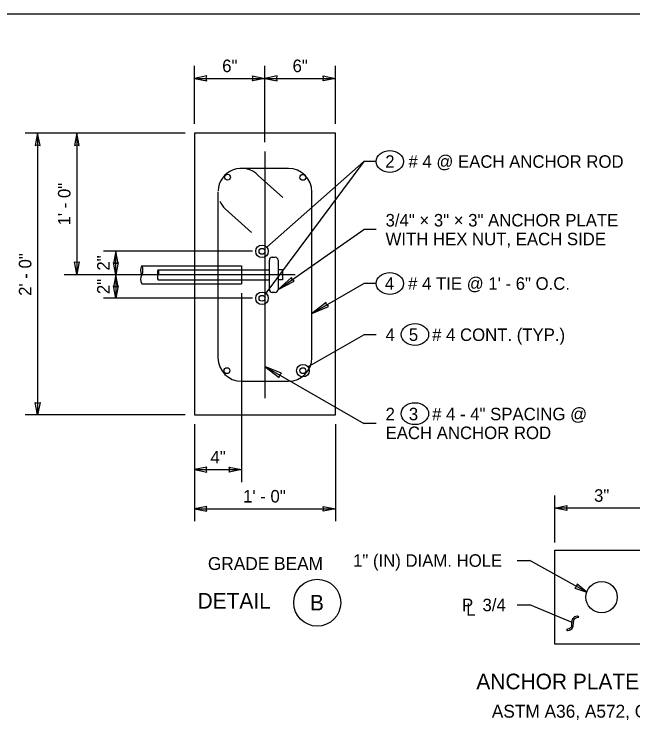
# Model space of a CAD drawing. Extents: x 99862 to 104211, y 98939 to 105076.
# Drawn here: x 101422 to 102213, y 104169 to 105076 of the extents above; entities that cross this region are included whole.
import ezdxf

# ---------------------------------------------------------------- set-up
doc = ezdxf.new("R2010")
doc.units = 0
for name, color, linetype in [('Level 1', 7, 'Continuous'), ('Level 10', 7, 'Continuous'), ('Level 12', 7, 'Continuous'), ('Level 15', 7, 'Continuous'), ('Level 18', 7, 'Continuous'), ('Level 20', 7, 'Continuous'), ('Level 8', 7, 'Continuous')]:
    doc.layers.add(name, color=color, linetype=linetype)

msp = doc.modelspace()

# ---------------------------------------------------------------- linework, layer by layer
at = {"layer": 'Level 1'}
msp.add_lwpolyline([(99862, 102999.5), (103151, 102999.5), (103151, 105075.5), (99862, 105075.5)], close=True, dxfattribs=at)
at = {"layer": 'Level 10'}
for p, q in [((101742.4, 104899.96), (101742.4, 104584.96)), ((101772.4, 104878.49), (101712.4, 104878.49)), ((101765.39, 104841.04), (101733.92, 104869.4)), ((101682.4, 104848.49), (101682.4, 104636.42)), ((101802.4, 104636.42), (101802.4, 104848.49)), ((101691.5, 104826.97), (101725.28, 104796.53)), ((101605.92, 104749.02), (101712.4, 104749.02)), ((101605.92, 104735.9), (101712.4, 104735.9)), ((101712.4, 104606.42), (101772.4, 104606.42))]:
    msp.add_line(p, q, dxfattribs=at)
for centre in [(101694.61, 104867.26), (101790.96, 104867.06), (101738.65, 104772.46), (101738.65, 104712.46), (101693.84, 104619.93), (101790.96, 104619.93)]:
    msp.add_circle(centre, 3.75, dxfattribs=at)
for centre, start, end in [((101712.4, 104848.49), 44.16338, 177.79608), ((101772.4, 104848.49), 0, 90), ((101712.4, 104848.49), 203.52897, 225.83662), ((101712.4, 104636.42), 180, 270), ((101772.4, 104636.42), 270, 0)]:
    msp.add_arc(centre, 30, start, end, dxfattribs=at)
at = {"layer": 'Level 12'}
msp.add_lwpolyline([(101652.4, 104923.49), (101652.4, 104563.49), (101832.4, 104563.49), (101832.4, 104923.49)], close=True, dxfattribs=at)
at = {"layer": 'Level 15'}
for p, q in [((101652.4, 104935.49), (101652.4, 105009.49)), ((101742.4, 104911.96), (101742.4, 105009.49)), ((101832.4, 104935.49), (101832.4, 105009.49)), ((101652.4, 104993.49), (101742.4, 104993.49)), ((101742.4, 104993.49), (101832.4, 104993.49)), ((101640.4, 104923.49), (101435.83, 104923.49)), ((101451.83, 104923.49), (101451.83, 104563.49)), ((101501.83, 104923.49), (101501.83, 104743.49)), ((101868.63, 104887.22), (101743.43, 104718.88)), ((101868.63, 104887.22), (101744.65, 104777.76)), ((101884.63, 104887.22), (101868.63, 104887.22)), ((101759.32, 104723.71), (101868.63, 104800.23)), ((101884.63, 104800.23), (101868.63, 104800.23)), ((101726.65, 104772.46), (101535.83, 104772.46)), ((101551.83, 104742.46), (101551.83, 104772.46)), ((101780.9, 104742.46), (101485.83, 104742.46)), ((101551.83, 104742.46), (101551.83, 104712.46)), ((101802.4, 104693.1), (101868.63, 104731.34)), ((101884.63, 104731.34), (101868.63, 104731.34)), ((101712.4, 104718.92), (101712.4, 104477.49)), ((101726.65, 104712.46), (101535.83, 104712.46)), ((101797.35, 104624.74), (101868.63, 104665.89)), ((101884.63, 104665.89), (101868.63, 104665.89)), ((101742.4, 104625.43), (101868.63, 104552.55)), ((101640.4, 104563.49), (101435.83, 104563.49)), ((101652.4, 104551.49), (101652.4, 104427.49)), ((101832.4, 104551.49), (101832.4, 104427.49)), ((101884.63, 104552.55), (101868.63, 104552.55)), ((101652.4, 104493.49), (101712.4, 104493.49)), ((102112.79, 104400.43), (102112.79, 104460.43)), ((101652.4, 104443.49), (101832.4, 104443.49)), ((102232.79, 104444.43), (102112.79, 104444.43)), ((102064.91, 104377.33), (102080.91, 104377.33)), ((102153.88, 104336.95), (102080.91, 104377.33)), ((102064.91, 104320.57), (102080.91, 104320.57)), ((102135.08, 104298.08), (102080.91, 104320.57)), ((102135.72, 104302.85), (102134.8, 104300.29)), ((102136.8, 104304.25), (102135.72, 104302.85)), ((102138.17, 104305.26), (102136.8, 104304.25)), ((102137.1, 104300.29), (102137.74, 104302.1)), ((102137.74, 104302.1), (102138.56, 104303.15)), ((102139.84, 104305.9), (102138.17, 104305.26)), ((102138.56, 104303.15), (102139.66, 104303.96)), ((102139.66, 104303.96), (102141.28, 104304.58)), ((102141.81, 104306.15), (102139.84, 104305.9)), ((102141.28, 104304.58), (102143.64, 104305.1)), ((102143.64, 104305.1), (102141.81, 104306.15)), ((102134.22, 104293.48), (102133.69, 104292.08)), ((102134.42, 104295.9), (102134.22, 104293.48)), ((102134.8, 104300.29), (102134.42, 104295.9)), ((102135.72, 104291.37), (102136.61, 104293.67)), ((102136.61, 104293.67), (102136.88, 104297.75)), ((102136.88, 104297.75), (102137.1, 104300.29)), ((102131.37, 104290.12), (102127.81, 104289.14)), ((102127.81, 104289.14), (102129.64, 104288.08)), ((102129.64, 104288.08), (102131.76, 104288.44)), ((102132.77, 104290.99), (102131.37, 104290.12)), ((102131.76, 104288.44), (102133.41, 104289.09)), ((102133.69, 104292.08), (102132.77, 104290.99)), ((102133.41, 104289.09), (102134.72, 104290.04)), ((102134.72, 104290.04), (102135.72, 104291.37))]:
    msp.add_line(p, q, dxfattribs=at)
for points in [[(101652.4, 104993.49), (101668.13, 104990.41), (101667.4, 104993.49), (101668.13, 104996.58)], [(101742.4, 104993.49), (101726.68, 104990.41), (101727.4, 104993.49), (101726.68, 104996.58)], [(101742.4, 104993.49), (101758.13, 104990.41), (101757.4, 104993.49), (101758.13, 104996.58)], [(101832.4, 104993.49), (101816.68, 104990.41), (101817.4, 104993.49), (101816.68, 104996.58)], [(101451.83, 104923.49), (101448.75, 104907.77), (101451.83, 104908.5), (101454.91, 104907.77)], [(101501.83, 104923.49), (101498.75, 104907.77), (101501.83, 104908.5), (101504.91, 104907.77)], [(101551.83, 104772.46), (101548.75, 104756.74), (101551.83, 104757.46), (101554.91, 104756.74)], [(101501.83, 104743.49), (101498.75, 104759.22), (101501.83, 104758.49), (101504.91, 104759.22)], [(101551.83, 104742.46), (101548.75, 104758.18), (101551.83, 104757.46), (101554.91, 104758.18)], [(101551.83, 104742.46), (101548.75, 104726.73), (101551.83, 104727.46), (101554.91, 104726.73)], [(101759.32, 104723.71), (101779.79, 104734.25), (101777.23, 104736.1), (101776.4, 104739.16)], [(101551.83, 104712.46), (101548.75, 104728.19), (101551.83, 104727.46), (101554.91, 104728.19)], [(101802.4, 104693.1), (101823.66, 104701.93), (101821.26, 104703.99), (101820.68, 104707.1)], [(101742.4, 104625.43), (101760.68, 104611.43), (101761.26, 104614.54), (101763.67, 104616.6)], [(101451.83, 104563.49), (101448.75, 104579.22), (101451.83, 104578.49), (101454.91, 104579.22)], [(101652.4, 104493.49), (101668.13, 104490.41), (101667.4, 104493.49), (101668.13, 104496.58)], [(101712.4, 104493.49), (101696.68, 104490.41), (101697.4, 104493.49), (101696.68, 104496.58)], [(102112.79, 104444.43), (102128.51, 104447.52), (102127.78, 104444.43), (102128.51, 104441.35)], [(101652.4, 104443.49), (101668.13, 104440.41), (101667.4, 104443.49), (101668.13, 104446.58)], [(101832.4, 104443.49), (101816.68, 104440.41), (101817.4, 104443.49), (101816.68, 104446.58)], [(102153.88, 104336.95), (102141.61, 104347.26), (102140.76, 104344.21), (102138.63, 104341.87)]]:
    msp.add_lwpolyline(points, close=True, dxfattribs=at)
for centre in [(101738.65, 104772.46), (101738.65, 104712.46), (101790.96, 104619.93)]:
    msp.add_circle(centre, 8, dxfattribs=at)
at = {"layer": 'Level 18'}
msp.add_lwpolyline([(102112.79, 104390.43), (102232.79, 104390.43), (102232.79, 104270.43), (102112.79, 104270.43)], close=True, dxfattribs=at)
msp.add_circle((102172.79, 104330.43), 20, dxfattribs=at)
at = {"layer": 'Level 20'}
msp.add_circle((101809.24, 104323.49), 30, dxfattribs=at)
for centre, major_axis in [((101902.13, 104887.22), (-17.5, 0)), ((101902.13, 104731.34), (-17.5, 0)), ((101934.19, 104666.13), (17.5, 0)), ((101934.14, 104564.99), (-17.5, 0))]:
    msp.add_ellipse(centre, major_axis=major_axis, ratio=0.8, dxfattribs=at)
at = {"layer": 'Level 8'}
for p, q in [((101751.82, 104764.96), (101755.57, 104764.96)), ((101748.07, 104723.71), (101748.07, 104761.21)), ((101759.32, 104761.21), (101759.32, 104723.71)), ((101584.96, 104754), (101712.4, 104754)), ((101605.92, 104749.02), (101712.4, 104749.02)), ((101712.4, 104754), (101712.4, 104730.92)), ((101712.4, 104749.02), (101748.07, 104749.02)), ((101764.9, 104749.02), (101759.32, 104749.02)), ((101764.9, 104749.02), (101764.9, 104735.9)), ((101584.96, 104730.92), (101712.4, 104730.92)), ((101605.92, 104735.9), (101712.4, 104735.9)), ((101712.4, 104735.9), (101748.07, 104735.9)), ((101764.9, 104735.9), (101759.32, 104735.9)), ((101755.57, 104719.96), (101751.82, 104719.96))]:
    msp.add_line(p, q, dxfattribs=at)
for centre, radius, start, end in [((101751.82, 104761.21), 3.75, 90, 180), ((101755.57, 104761.21), 3.75, 0, 90), ((101594.95, 104748.23), 11.54, 150, 210), ((101574.96, 104748.23), 11.54, 330, 30), ((101611.61, 104745.74), 6.56, 150, 210), ((101600.24, 104745.74), 6.56, 330, 30), ((101594.95, 104736.69), 11.54, 150, 210), ((101611.61, 104739.18), 6.56, 150, 210), ((101751.82, 104723.71), 3.75, 180, 270), ((101755.57, 104723.71), 3.75, 270, 0)]:
    msp.add_arc(centre, radius, start, end, dxfattribs=at)

# ---------------------------------------------------------------- texts
at = {"layer": 'Level 20'}
for s, height, p in [('6"', 16, (101687.74, 105001.49)), ('6"', 16, (101777.74, 105001.49)), ('4   5   # 4 CONT. (TYP.)', 16, (101896.62, 104657.89)), ('4"', 16, (101672.74, 104501.49)), ('1\' - 0"', 16, (101714.47, 104451.49)), ('3"', 16, (102163.13, 104452.43)), ('1" (IN) DIAM. HOLE', 16, (101855.05, 104369.33)), ('GRADE BEAM', 16.5, (101669.5, 104365.24)), ('DETAIL', 20, (101656.26, 104315.88)), ('B', 20, (101799.99, 104313.49)), ('P  3/4', 16, (101994.35, 104312.57)), ('L', 16, (101999.65, 104306.83)), ('ANCHOR PLATE DETAIL', 20, (102012.67, 104212.77)), ('ASTM A36, A572, OR A588', 16.5, (102032.43, 104176.52))]:
    msp.add_text(s, height=height, dxfattribs=at).set_placement(p)
for s, rotation, p in [('2   # 4 @ EACH ANCHOR ROD', 360, (101896.16, 104879.21)), ('1\' - 0"', 90, (101493.83, 104805.56)), ('3/4" × 3" × 3" ANCHOR PLATE ', 360, (101896.62, 104804.23)), ('WITH HEX NUT, EACH SIDE', 360, (101896.62, 104780.23)), ('2\' - 0"', 90, (101443.83, 104715.56)), ('2"', 90, (101543.83, 104747.8)), ('4   # 4 TIE @ 1\' - 6" O.C.', 360, (101895.67, 104723.32)), ('2"', 90, (101543.83, 104717.8)), ('2   3   # 4 - 4" SPACING @', 360, (101896.62, 104556.55)), ('EACH ANCHOR ROD', 360, (101896.62, 104532.55))]:
    msp.add_text(s, height=16, rotation=rotation, dxfattribs=at).set_placement(p)

doc.saveas('drawing.dxf')
